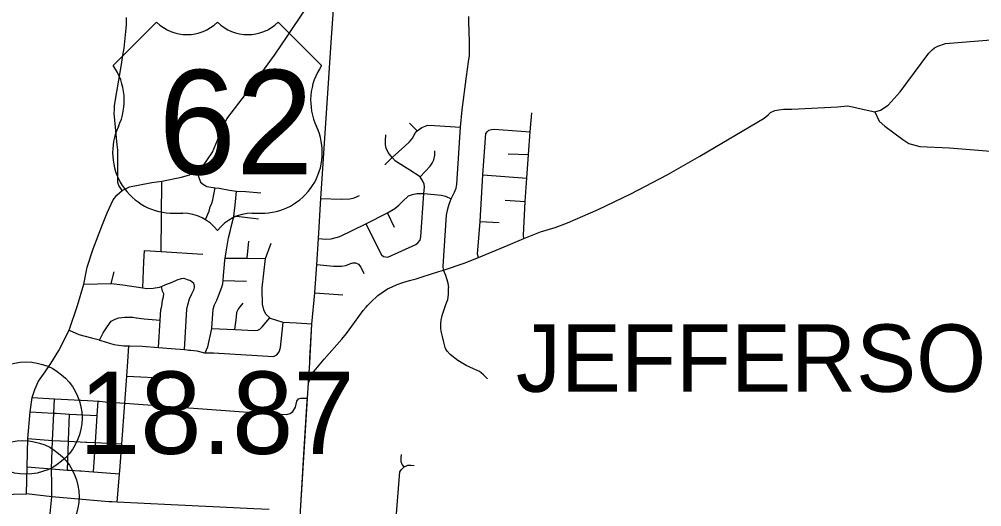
# Model space of a CAD drawing. Extents: x 1659811 to 1934326, y 644115 to 934867.
# Drawn here: x 1862074 to 1874937, y 735393 to 741905 of the extents above; entities that cross this region are included whole.
import ezdxf

# ---------------------------------------------------------------- set-up
doc = ezdxf.new("R2010")
doc.units = 0
for name, color, linetype in [('Default', 7, 'Continuous'), ('GM_X_City_Street', 7, 'Continuous'), ('GM_X_County_Road', 7, 'Continuous'), ('GM_X_State_Route', 7, 'Continuous'), ('GM_X_Township', 7, 'Continuous'), ('GM_X_Township_Road', 7, 'Continuous'), ('GM_X_Township_Text', 7, 'Continuous'), ('GM_X_US_Route', 7, 'Continuous'), ('GM_X_US_Shield', 7, 'Continuous')]:
    doc.layers.add(name, color=color, linetype=linetype)

msp = doc.modelspace()

# ---------------------------------------------------------------- linework, layer by layer
at = {"layer": 'Default'}
for centre in [(1862163, 736578), (1862123, 735527)]:
    msp.add_circle(centre, 750, dxfattribs=at)
at = {"layer": 'GM_X_City_Street'}
for points in [[(1865959, 737371), (1865984, 737831), (1866022, 738252), (1866049, 738627), (1866072, 738976), (1866105, 739510), (1866249, 741656), (1866278, 742098), (1866289, 742237), (1866310, 742496), (1866313, 742627)], [(1863451, 739619), (1863405, 739686), (1863392, 739723), (1863392, 739794), (1863390, 740157), (1863384, 740229), (1863344, 740649), (1863346, 740695), (1863348, 740752), (1863435, 741276), (1863460, 741420), (1863474, 741520), (1863498, 741740), (1863507, 741824), (1863508, 741895), (1863507, 741927)], [(1867812, 738316), (1867813, 738319), (1867806, 738380), (1867790, 738436), (1867773, 738481), (1867743, 738553), (1867741, 738607), (1867782, 739287), (1867800, 739373), (1867820, 739436), (1867848, 739504), (1867891, 739593), (1867911, 739648), (1867920, 739702), (1867969, 740462), (1867991, 740696), (1868052, 741141), (1868079, 741334), (1868091, 741422), (1868093, 741524), (1868093, 741607), (1868081, 741871), (1868080, 741944)], [(1868817, 738974), (1868811, 739020), (1868834, 739471), (1868857, 739782), (1868878, 740096), (1868900, 740399), (1868922, 740657)], [(1867056, 740058), (1867225, 740210), (1867290, 740267), (1867334, 740323), (1867361, 740377), (1867390, 740415), (1867455, 740460), (1867498, 740477), (1867536, 740490), (1867623, 740485), (1867969, 740462)], [(1867290, 740515), (1867390, 740415)], [(1868211, 738721), (1868200, 738767), (1868232, 739205), (1868271, 739825), (1868311, 740378), (1868329, 740403), (1868351, 740424), (1868384, 740434), (1868420, 740436), (1868900, 740399)], [(1866704, 739171), (1866915, 738758), (1866942, 738735), (1866971, 738731), (1867000, 738728), (1867373, 738895), (1867400, 738916), (1867430, 738954), (1867440, 738997), (1867482, 739575), (1867490, 739660), (1867486, 739700), (1867469, 739741), (1867432, 739802), (1867294, 739891), (1867102, 740010), (1867056, 740058), (1867002, 740125), (1866979, 740183), (1866969, 740229), (1866967, 740279), (1866971, 740362)], [(1866959, 739962), (1867056, 740058)], [(1867432, 739802), (1867567, 739941), (1867594, 739983), (1867615, 740029), (1867628, 740091), (1867630, 740148)], [(1868606, 740109), (1868878, 740096)], [(1864444, 739879), (1864497, 739728), (1864536, 739696), (1864580, 739671), (1864691, 739652), (1864744, 739647), (1864885, 739621), (1864975, 739609), (1865101, 739602), (1865301, 739585)], [(1868271, 739825), (1868857, 739782)], [(1863969, 738801), (1863981, 739742)], [(1864565, 739231), (1864611, 739342), (1864626, 739400), (1864649, 739446), (1864663, 739494), (1864673, 739564), (1864691, 739652)], [(1864896, 739089), (1864906, 739130), (1864938, 739250), (1864942, 739279), (1864956, 739380), (1864963, 739466), (1864975, 739609)], [(1866072, 738976), (1866172, 738969), (1866242, 738973), (1866360, 739001), (1866704, 739171), (1866994, 739319), (1867094, 739377), (1867148, 739422), (1867190, 739466), (1867275, 739545), (1867330, 739566), (1867386, 739577), (1867482, 739575), (1867719, 739556), (1867771, 739543), (1867848, 739504)], [(1866105, 739510), (1866375, 739502), (1866491, 739508), (1866549, 739518), (1866619, 739550)], [(1868567, 739488), (1868834, 739471)], [(1864942, 739279), (1865270, 739239)], [(1867090, 739122), (1866994, 739319)], [(1868232, 739205), (1868488, 739188)], [(1864559, 737447), (1864592, 737527), (1864646, 737774), (1864648, 737780), (1864667, 738030), (1864684, 738092), (1864715, 738153), (1864780, 738328), (1864793, 738372), (1864797, 738417), (1864797, 738428), (1864823, 738680), (1864827, 738714), (1864837, 738797), (1864870, 738985), (1864896, 739089), (1864896, 739089)], [(1865120, 738713), (1865141, 738941)], [(1865363, 738711), (1865441, 738915)], [(1863740, 738666), (1863740, 738666), (1863747, 738814)], [(1863747, 738814), (1863969, 738801), (1864526, 738766)], [(1863724, 738318), (1863740, 738666)], [(1864827, 738714), (1865120, 738713), (1865363, 738711)], [(1865777, 737843), (1865600, 737854), (1865431, 737907), (1865421, 737916), (1865369, 737967), (1865342, 738022), (1865324, 738098), (1865323, 738154), (1865319, 738244), (1865318, 738318), (1865363, 738711)], [(1866049, 738627), (1866272, 738608), (1866381, 738608), (1866438, 738617), (1866490, 738638), (1866534, 738653), (1866568, 738652), (1866606, 738633), (1866638, 738595), (1866678, 738510)], [(1863303, 738373), (1863344, 738532)], [(1862936, 738367), (1863303, 738373), (1863456, 738359), (1863724, 738318), (1863773, 738310), (1863863, 738314), (1863950, 738327), (1863973, 738337), (1864032, 738362), (1864116, 738393), (1864182, 738423), (1864242, 738442), (1864274, 738446), (1864320, 738429), (1864362, 738413), (1864408, 738378)], [(1864280, 737492), (1864315, 738031), (1864328, 738090), (1864351, 738168), (1864380, 738238), (1864411, 738299), (1864418, 738327), (1864416, 738341), (1864408, 738378)], [(1864797, 738417), (1865109, 738406)], [(1866670, 738013), (1866671, 738015), (1866708, 738057), (1866730, 738082), (1866771, 738125), (1866865, 738213), (1866925, 738256), (1866997, 738302), (1867057, 738332), (1867125, 738361), (1867198, 738388), (1867288, 738414), (1867379, 738439)], [(1863935, 737520), (1863958, 737883), (1863967, 738021), (1863978, 738072), (1863990, 738154), (1864001, 738198), (1864005, 738236), (1863987, 738272), (1863973, 738337)], [(1866022, 738252), (1866398, 738222)], [(1864957, 737759), (1864976, 737923), (1864983, 737993), (1864998, 738029), (1865024, 738061), (1865065, 738112)], [(1863144, 737620), (1863197, 737718), (1863248, 737796), (1863303, 737870), (1863354, 737898), (1863405, 737914), (1863484, 737923), (1863590, 737923), (1863638, 737917), (1863639, 737917)], [(1863639, 737917), (1863745, 737903), (1863958, 737883)], [(1864341, 737486), (1864368, 737484), (1864449, 737475), (1864550, 737447), (1864559, 737447), (1864671, 737448), (1865470, 737401), (1865515, 737421), (1865548, 737462), (1865563, 737522), (1865600, 737854)], [(1864646, 737774), (1864957, 737759), (1865219, 737746), (1865263, 737750), (1865288, 737767), (1865318, 737795), (1865421, 737916)], [(1862743, 737751), (1862870, 737695), (1863040, 737648), (1863112, 737629), (1863142, 737621)], [(1865984, 737831), (1865777, 737843)], [(1863142, 737621), (1863144, 737620), (1863163, 737615), (1863339, 737562), (1863471, 737541), (1863524, 737540), (1863539, 737540), (1863553, 737540)], [(1865941, 737049), (1865994, 737176), (1866151, 737366), (1866385, 737633)], [(1863525, 737331), (1863525, 737331), (1863539, 737540)], [(1863553, 737540), (1863715, 737537), (1863935, 737520), (1864106, 737506), (1864280, 737492), (1864320, 737488), (1864341, 737486)], [(1865941, 737049), (1865956, 737315), (1865959, 737371)], [(1863443, 736235), (1863484, 736776), (1863511, 737138), (1863525, 737331)], [(1863511, 737138), (1864069, 737110)], [(1865922, 736804), (1865925, 736844), (1865941, 737049)], [(1862246, 736852), (1862546, 736835), (1862988, 736811), (1863061, 736806)], [(1862507, 735684), (1862503, 735900), (1862520, 736276), (1862537, 736642), (1862546, 736835)], [(1863224, 736796), (1863484, 736776), (1865377, 736636), (1865648, 736624), (1865695, 736638), (1865731, 736666), (1865765, 736723), (1865782, 736801), (1865806, 736832), (1865839, 736841), (1865925, 736844)], [(1863061, 736806), (1863129, 736803), (1863147, 736802), (1863224, 736796)], [(1863067, 735857), (1863093, 736250), (1863117, 736610), (1863129, 736803)], [(1865883, 736166), (1865922, 736804)], [(1862219, 736660), (1862532, 736643), (1862537, 736642), (1862568, 736641)], [(1862568, 736641), (1862745, 736631), (1863117, 736610)], [(1862733, 736282), (1862745, 736631)], [(1862190, 736306), (1862520, 736276), (1862732, 736267), (1862962, 736256), (1862979, 736255)], [(1862719, 735883), (1862732, 736267), (1862733, 736282), (1862733, 736282)], [(1862979, 736255), (1863093, 736250), (1863251, 736242), (1863257, 736242)], [(1863257, 736242), (1863443, 736234)], [(1863416, 735870), (1863443, 736234), (1863443, 736235)], [(1865832, 735332), (1865883, 736166)], [(1867216, 735925), (1867190, 735959), (1867177, 735993), (1867178, 736041), (1867184, 736091)], [(1862179, 735924), (1862503, 735900), (1862719, 735883), (1862745, 735881)], [(1867109, 735243), (1867161, 735857), (1867181, 735892), (1867216, 735925), (1867269, 735947), (1867307, 735950), (1867353, 735942)], [(1862745, 735881), (1862879, 735871), (1862899, 735870)], [(1862899, 735870), (1863002, 735862)], [(1863002, 735862), (1863067, 735857), (1863413, 735831)], [(1863384, 735452), (1863413, 735831), (1863416, 735870)], [(1862510, 735527), (1862507, 735684)], [(1862462, 734999), (1862468, 735123), (1862510, 735527)]]:
    msp.add_lwpolyline(points, dxfattribs=at)
at = {"layer": 'GM_X_County_Road'}
for points in [[(1867681, 738533), (1867743, 738553), (1868019, 738647), (1868211, 738721), (1868610, 738888), (1868817, 738974), (1869041, 739063), (1869238, 739124), (1869403, 739186), (1869810, 739363), (1870246, 739574), (1870732, 739826), (1871169, 740078), (1872029, 740585), (1872082, 740626), (1872116, 740658), (1872172, 740684), (1872226, 740696), (1872290, 740704), (1872401, 740705), (1873009, 740736), (1873144, 740747), (1873208, 740736), (1873325, 740709), (1873507, 740668), (1873583, 740689), (1873685, 740756), (1873846, 740937), (1874231, 741453), (1874273, 741497), (1874305, 741522), (1874349, 741544), (1874452, 741581), (1875282, 741648)], [(1867379, 738439), (1867460, 738462), (1867681, 738533)], [(1866385, 737633), (1866448, 737706), (1866555, 737856), (1866670, 738013)]]:
    msp.add_lwpolyline(points, dxfattribs=at)
at = {"layer": 'GM_X_State_Route'}
for points in [[(1863317, 735457), (1863273, 735460), (1862510, 735527), (1862169, 735565)], [(1864103, 735418), (1863384, 735452), (1863317, 735457)], [(1865413, 735354), (1865209, 735364), (1864756, 735386), (1864103, 735418)]]:
    msp.add_lwpolyline(points, dxfattribs=at)
at = {"layer": 'GM_X_Township'}
msp.add_lwpolyline([(1865005, 721674), (1865437, 728430), (1865493, 729406), (1865541, 730325), (1865558, 730636), (1865573, 730904), (1865594, 731078), (1865672, 732154), (1865744, 733579), (1865832, 735332), (1865925, 736844), (1865941, 737049), (1865956, 737315), (1865984, 737831), (1866022, 738252), (1866049, 738627), (1866072, 738976), (1866105, 739510), (1866249, 741656), (1866278, 742098)], dxfattribs=at)
at = {"layer": 'GM_X_Township_Road'}
for points in [[(1873507, 740668), (1873565, 740543), (1873641, 740475), (1873881, 740300), (1873963, 740247), (1874013, 740230), (1874109, 740206), (1874504, 740186), (1875113, 740139), (1875596, 740076), (1875853, 740059), (1875877, 740057), (1875936, 740053)], [(1868333, 737102), (1868279, 737156), (1868248, 737183), (1868224, 737200), (1868145, 737233), (1868045, 737279), (1867937, 737348), (1867833, 737428), (1867794, 737471), (1867775, 737497), (1867767, 737522), (1867750, 737589), (1867730, 737666), (1867711, 737736), (1867706, 737781), (1867709, 737842), (1867711, 737883), (1867725, 737949), (1867777, 738096), (1867801, 738159), (1867809, 738227), (1867812, 738316)]]:
    msp.add_lwpolyline(points, dxfattribs=at)
at = {"layer": 'GM_X_US_Route'}
for points in [[(1863451, 739619), (1863549, 739667), (1863845, 739722), (1863981, 739742), (1864243, 739794), (1864348, 739828), (1864444, 739879), (1864532, 739946), (1864657, 740128), (1864791, 740449), (1864849, 740575), (1865113, 740919), (1865266, 741128), (1865486, 741424), (1865655, 741675), (1865891, 742026), (1866051, 742242), (1866313, 742627), (1866400, 742751), (1866466, 742867), (1866688, 743278), (1866783, 743453)], [(1862246, 736852), (1862280, 736957), (1862331, 737069), (1862421, 737195), (1862498, 737306), (1862604, 737478), (1862743, 737751), (1862852, 738080), (1862936, 738367), (1862980, 738594), (1863063, 738840), (1863186, 739162), (1863249, 739317), (1863331, 739493), (1863377, 739554), (1863451, 739619)], [(1862169, 735565), (1862179, 735924), (1862190, 736306), (1862219, 736660), (1862246, 736852)], [(1858757, 735399), (1859073, 735428), (1859405, 735457), (1860498, 735532), (1860946, 735542), (1861627, 735551), (1862169, 735565)]]:
    msp.add_lwpolyline(points, dxfattribs=at)
at = {"layer": 'GM_X_US_Shield'}
for p, q in [((1863910, 741866), (1863330, 741286)), ((1866115, 741286), (1865535, 741866)), ((1864142, 739313), (1864258, 739313)), ((1865186, 739313), (1865302, 739313))]:
    msp.add_line(p, q, dxfattribs=at)
for centre, radius, start, end in [((1864316, 742280), 580, 225.573, 314.427), ((1865128, 742280), 580, 225.573, 314.427), ((1862665, 740820), 812, 334.5471, 35.0009), ((1866780, 740820), 812, 144.9991, 205.4529), ((1864133, 740125), 812, 154.8319, 270.6383), ((1865312, 740125), 812, 269.3617, 25.1681), ((1864258, 738733), 580, 36.8699, 90), ((1865186, 738733), 580, 90, 143.1301)]:
    msp.add_arc(centre, radius, start, end, dxfattribs=at)

# ---------------------------------------------------------------- texts
at = {"layer": 'Default'}
msp.add_text('18.87', height=1100, dxfattribs=at).set_placement((1862873, 736099))
at = {"layer": 'GM_X_Township_Text'}
msp.add_text('JEFFERSON', height=900, rotation=0, dxfattribs=at).set_placement((1868711, 736928))
at = {"layer": 'GM_X_US_Shield'}
msp.add_text('62', height=1392.2, dxfattribs=at).set_placement((1863934, 739835))

doc.saveas('drawing.dxf')
